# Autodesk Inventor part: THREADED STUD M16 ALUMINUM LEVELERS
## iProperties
Created: 2007-03
Part Number: THREADED STUD M16 ALUMINUM LEVELERS
Document SubType Name: Modeling
Designer: Andy Moles
Material: Steel
Mass: 153.684 g
Surface Area: 57.8886 cm^2
Volume: 19.5776 cm^3
Density: 7.85 g/cm^3
Author: Andy Moles
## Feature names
1. Revolution1
2. Extrusion1
3. Extrusion2
4. Chamfer1
